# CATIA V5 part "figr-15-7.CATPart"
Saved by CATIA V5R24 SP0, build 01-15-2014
Part number: Part1
Bounding box of the stored display mesh (mm): x -50 to 50, y -32.5 to 33.5, z -52 to 1
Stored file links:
  D:\KAVITA\CATIA V5-6R2014 Project_ Kavita\CATIA V5-6R2014_partfiles\Partfiles\c15_catia_v5-6r2014_prt\figr-15-7.CATPart
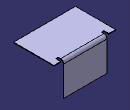
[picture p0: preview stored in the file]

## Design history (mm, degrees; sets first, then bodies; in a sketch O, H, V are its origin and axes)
SheetMetalParameters1: Thickness 1, BendRadius 4, KFactor 0.475772 {= log(min(100,max(20*SheetMetalParameters1.BendRadius,SheetMetalParameters1.Thickness)/SheetMetalParameters1.Thickness))/log(100)/2}, ReliefRadialLength 4, ReliefAxialLength 4, MinimumBendRadius 0
Body1 (main body)
  Sketch1 on xy-plane, origin (0, 0, 0), H (1, 0, 0), V (0, 1, 0)
    line L1 (-50, 32.5) -> (50, 32.5)
    line L2 (50, 32.5) -> (50, -32.5)
    line L3 (50, -32.5) -> (-50, -32.5)
    line L4 (-50, -32.5) -> (-50, 32.5)
    length L1 = 100
    length L2 = 65
    horizontal: L1 H, L3 H
    vertical: L2 V, L4 V
    symmetry: L4 L2 V, L1 L3 H
  Wall1: Thickness 1, Profile Sketch1
  d_NewWallOnEdge1: NewWallOnEdge_Edge edge [face of Wall1 | face of Wall1], NewWallOnEdge_Length 53, NewWallOnEdge_HeightLimitOffset 0, NewWallOnEdge_WidthOffset1 -15, NewWallOnEdge_WidthOffset2 -15, NewWallOnEdge_Angle 90, NewWallOnEdge_BendRadiusValue 4 {= SheetMetalParameters1.BendRadius}, NewWallOnEdge_BendTable SheetMetalParameters1, KFacteur 0.475772 {= log(min(100,max(20*d_NewWallOnEdge1.Radius,SheetMetalParameters1.Thickness)/SheetMetalParameters1.Thickness))/log(100)/2}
